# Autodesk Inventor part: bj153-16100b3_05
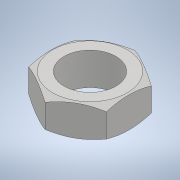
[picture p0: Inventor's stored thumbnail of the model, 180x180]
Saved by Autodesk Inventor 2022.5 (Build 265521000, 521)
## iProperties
Part Number: bj153-16100b3_05
Material: 一般
Document SubType Name: Modeling
Designer: ImaoCorp
Density: 1 g/cm^3
Appearance: 既定
Author: ImaoCorp
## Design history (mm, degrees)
feature "bj153-16100b3_05"
node "ソリッド1"
